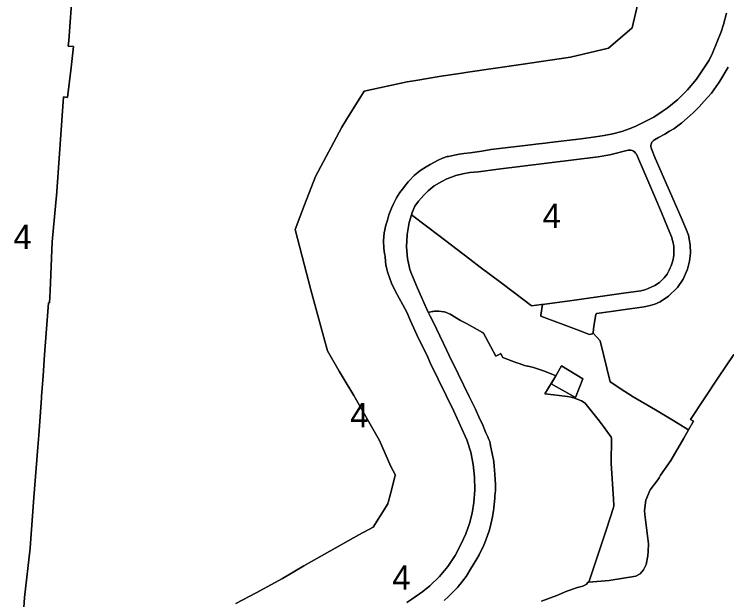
# Model space of a CAD drawing. Extents: x 598968 to 613553, y 4409678 to 4430833.
# Drawn here: x 601272.7 to 601623.1, y 4414130.4 to 4414418.6 of the extents above; entities that cross this region are included whole.
import ezdxf

# ---------------------------------------------------------------- set-up
doc = ezdxf.new("R2010")
doc.units = 0
for name, color, linetype in [('1', 7, 'Continuous'), ('Sòl Rústic Comú', 7, 'Continuous'), ('ZONA 4. CASES UNIFAMILIRAS AÏLLADES EN PARCEL.LES', 7, 'Continuous')]:
    doc.layers.add(name, color=color, linetype=linetype)

msp = doc.modelspace()

# ---------------------------------------------------------------- linework, layer by layer
at = {"layer": '1'}
for points in [[(601301.298, 4414430.8135), (601299.4995, 4414405.7306), (601299.2889, 4414402.9028), (601301.818, 4414402.6437), (601300.6442, 4414392.3584), (601298.958, 4414377.5838), (601296.89, 4414377.9245), (601293.6381, 4414331.4042), (601293.6162, 4414331.165), (601291.3681, 4414306.6243), (601290.2881, 4414282.5045), (601289.9881, 4414276.5945), (601289.5781, 4414276.6145), (601287.5681, 4414250.9247), (601286.8481, 4414240.6598), (601286.1281, 4414230.3949), (601286.0723, 4414229.6282), (601284.7552, 4414211.5161), (601284.3181, 4414205.5051), (601282.4081, 4414180.7053), (601280.4691, 4414156.0453), (601280.4582, 4414155.9054), (601277.7782, 4414131.5456), (601275.9836, 4414104.2898)], [(601381.7065, 4414128.6767), (601391.6574, 4414133.8897), (601404.5462, 4414140.9469), (601415.166, 4414147.1569), (601425.2059, 4414152.807), (601442.1756, 4414162.4271), (601449.1355, 4414166.1871), (601456.3523, 4414177.685), (601456.4433, 4414178.0227), (601456.4854, 4414178.2371), (601457.6811, 4414182.6172), (601460.0848, 4414191.5389), (601460.1326, 4414191.7162), (601457.9353, 4414195.947), (601452.265, 4414208.8867), (601439.6957, 4414231.0065), (601434.5054, 4414239.6885), (601432.5458, 4414242.9663), (601426.8059, 4414253.0162), (601424.9859, 4414259.5461), (601418.5872, 4414282.8915), (601418.5863, 4414282.895), (601410.7762, 4414312.5955), (601415.497, 4414324.8686), (601420.8156, 4414338.6954), (601433.7354, 4414363.0054), (601436.0992, 4414366.8229), (601444.6955, 4414380.7054), (601465.955, 4414385.3255), (601470.1314, 4414386.0296), (601482.6647, 4414388.0957), (601492.8245, 4414389.6058), (601495.7645, 4414390.0158), (601508.1522, 4414391.8435), (601521.8564, 4414393.8693), (601546.2736, 4414397.4963), (601564.9663, 4414401.9773), (601576.573, 4414411.9565), (601579.3492, 4414423.9373)], [(601622.9646, 4414419.1877), (601621.5008, 4414413.6226), (601620.3924, 4414409.9469), (601615.9725, 4414399.427), (601614.4725, 4414396.047), (601608.1609, 4414386.6353), (601603.7928, 4414381.4449), (601598.9521, 4414376.6922), (601593.6825, 4414372.4199), (601591.3335, 4414370.8089), (601587.263, 4414368.0169), (601581.9331, 4414365.2569), (601578.3531, 4414363.5169), (601575.6032, 4414362.3768), (601571.4033, 4414360.8968), (601567.1132, 4414359.7168), (601562.7423, 4414358.8429), (601558.5134, 4414358.2867), (601551.4535, 4414357.2866), (601536.1138, 4414355.4465), (601533.8125, 4414355.1924), (601529.189, 4414354.6231), (601526.7031, 4414354.3256), (601507.0843, 4414351.9562), (601502.6844, 4414351.2462), (601496.9209, 4414350.4625), (601493.8545, 4414350.0461), (601491.4945, 4414349.7161), (601489.1146, 4414349.286), (601486.2581, 4414348.6604), (601485.6147, 4414348.506), (601483.3348, 4414347.736), (601481.1048, 4414346.836), (601477.2849, 4414344.696), (601475.1949, 4414343.4959), (601472.215, 4414341.4659), (601469.425, 4414339.1759), (601466.8551, 4414336.6559), (601466.3951, 4414336.1259), (601464.5651, 4414333.8559), (601464.2054, 4414333.2562), (601462.3451, 4414330.7959), (601460.6852, 4414328.1959), (601459.1708, 4414325.3556), (601458.2326, 4414323.2065), (601456.8652, 4414319.8459), (601456.2608, 4414317.306), (601455.4352, 4414314.766), (601454.6052, 4414311.0164), (601454.2594, 4414307.1917), (601454.4035, 4414303.354), (601454.8236, 4414300.8345), (601455.0354, 4414299.5661), (601455.2454, 4414296.6961), (601455.4554, 4414295.2661), (601455.9054, 4414293.1461), (601456.2954, 4414291.7562), (601457.3554, 4414288.5862), (601458.2554, 4414286.2962), (601460.1153, 4414282.2063), (601463.8453, 4414275.5964), (601465.7652, 4414272.0164), (601467.4852, 4414267.7165), (601470.8952, 4414260.5366), (601474.0051, 4414254.1166), (601475.5351, 4414250.9567), (601477.4626, 4414246.7226), (601488.8561, 4414223.1815), (601495.3236, 4414209.0924), (601497.1498, 4414203.1272), (601498.4008, 4414197.0155), (601499.0652, 4414190.8127), (601499.1371, 4414184.5746), (601498.6158, 4414178.358), (601497.8215, 4414173.0816), (601496.5279, 4414167.9049), (601494.7469, 4414162.8749), (601492.4948, 4414158.0376), (601489.5143, 4414152.2752), (601485.9291, 4414146.8681), (601481.7811, 4414141.8797), (601477.1189, 4414137.3681), (601473.6751, 4414134.4476), (601468.1468, 4414130.6926), (601465.6652, 4414129.0576)], [(601484.1758, 4414130.0728), (601486.3148, 4414132.0478), (601490.6148, 4414136.5278), (601491.1657, 4414137.1617), (601492.6747, 4414138.8978), (601493.1705, 4414139.5816), (601494.8647, 4414141.9178), (601497.0547, 4414145.4578), (601500.2246, 4414150.5678), (601501.2646, 4414152.5278), (601502.3497, 4414154.6626), (601503.2546, 4414156.5178), (601504.5946, 4414159.7878), (601505.5604, 4414162.619), (601506.2706, 4414164.3279), (601506.6956, 4414166.129), (601507.0794, 4414167.7145), (601507.5883, 4414169.8172), (601507.9345, 4414171.2477), (601508.414, 4414174.3133), (601508.5813, 4414175.3833), (601508.5945, 4414175.4677), (601508.9686, 4414180.6387), (601509.0345, 4414181.5376), (601509.3078, 4414184.2659), (601509.2645, 4414187.0076), (601509.1434, 4414189.8545), (601508.855, 4414194.357), (601508.7445, 4414196.0875), (601508.4545, 4414198.4875), (601507.7345, 4414202.3575), (601506.9345, 4414206.2174), (601506.7901, 4414207.3014), (601506.5155, 4414208.36), (601506.1145, 4414209.3774), (601505.5509, 4414210.6098), (601504.6646, 4414212.5473), (601502.7346, 4414217.1473), (601501.7207, 4414219.3501), (601499.4347, 4414224.3171), (601498.1618, 4414226.802), (601497.9747, 4414227.1671), (601496.4322, 4414230.404), (601491.0076, 4414241.6093), (601489.2748, 4414245.0969), (601487.9849, 4414247.5168), (601483.7447, 4414256.6204), (601478.595, 4414267.4766), (601477.252, 4414270.0398), (601476.3951, 4414271.6765), (601476.0951, 4414272.2765), (601471.0322, 4414283.8391), (601468.1157, 4414290.8215), (601467.2302, 4414292.9413), (601466.0927, 4414298.45), (601465.5753, 4414304.0512), (601465.839, 4414310.1533), (601466.8552, 4414316.1761), (601467.9802, 4414319.8611), (601468.3952, 4414320.9961), (601469.7552, 4414324.086), (601471.4752, 4414326.556), (601474.0751, 4414329.636), (601476.2351, 4414331.756), (601479.175, 4414334.1361), (601482.915, 4414336.3561), (601485.4549, 4414337.5661), (601487.6349, 4414338.4461), (601489.8649, 4414339.1961), (601493.2748, 4414340.0762), (601496.7548, 4414340.6462), (601500.9847, 4414341.0662), (601510.6945, 4414342.2763), (601559.8336, 4414348.3868), (601565.6135, 4414349.3668), (601574.5934, 4414351.6969), (601575.2755, 4414351.742), (601575.9551, 4414351.6691), (601576.6121, 4414351.4803), (601577.2267, 4414351.1813), (601577.7808, 4414350.7811), (601578.2577, 4414350.2914), (601578.6433, 4414349.727), (601583.2732, 4414339.1171), (601588.2132, 4414327.5072), (601590.9216, 4414321.0275), (601593.9731, 4414313.7274), (601596.033, 4414308.7975), (601596.2814, 4414307.8177), (601596.623, 4414306.6775), (601596.983, 4414304.4975), (601597.073, 4414303.4075), (601597.073, 4414301.1975), (601596.993, 4414300.1076), (601596.633, 4414297.9276), (601596.073, 4414295.7876), (601595.703, 4414294.7276), (601595.2717, 4414293.7504), (601594.803, 4414292.6776), (601593.6831, 4414290.7376), (601592.3531, 4414288.9376), (601590.0131, 4414286.5376), (601587.7132, 4414285.1576), (601584.4932, 4414283.6076), (601582.8332, 4414282.9575), (601580.8533, 4414282.4575), (601572.2537, 4414281.2743), (601546.9966, 4414277.7523), (601532.498, 4414275.8267), (601532.4941, 4414275.8171), (601531.6541, 4414270.4571), (601531.6341, 4414270.0771), (601549.1338, 4414263.4274), (601555.6137, 4414261.0574), (601556.3237, 4414261.0874), (601556.8637, 4414261.3374), (601557.3037, 4414261.6774), (601557.2937, 4414261.9374), (601557.6437, 4414265.1074), (601558.4914, 4414269.8868), (601558.6436, 4414270.9274), (601558.8936, 4414271.2074), (601559.0636, 4414271.2974), (601559.2436, 4414271.3474), (601582.4542, 4414274.6043), (601585.4232, 4414275.1876), (601587.7032, 4414275.9377), (601590.2918, 4414277.0359), (601594.4626, 4414279.8478), (601598.8209, 4414284.0546), (601601.6619, 4414288.2934), (601603.749, 4414293.1543), (601604.7565, 4414297.0488), (601605.2029, 4414301.0465), (601605.0791, 4414305.0673), (601604.2709, 4414309.8449), (601602.9577, 4414313.2217), (601600.6677, 4414318.6048), (601587.9006, 4414347.7628), (601586.0819, 4414352.3835), (601585.8817, 4414352.9133), (601585.7747, 4414353.4695), (601585.7642, 4414354.0358), (601585.8504, 4414354.5955), (601586.0308, 4414355.1324), (601586.3001, 4414355.6307), (601586.6503, 4414356.0757), (601587.0714, 4414356.4545), (601587.5509, 4414356.756), (601589.5777, 4414357.8808), (601592.6131, 4414359.537), (601594.9849, 4414360.974), (601596.993, 4414362.2071), (601601.0329, 4414365.1471), (601606.5529, 4414370.1071), (601609.4228, 4414373.0471), (601612.0228, 4414375.7571), (601615.5227, 4414379.8071), (601617.8683, 4414383.0965), (601619.7226, 4414385.6971), (601623.7826, 4414392.4771)]]:
    msp.add_lwpolyline(points, dxfattribs=at)
for points in [[(601526.8946, 4414275.2101), (601518.6798, 4414281.4346), (601511.9589, 4414286.5269), (601501.8758, 4414294.1662), (601496.6737, 4414298.1074), (601481.4259, 4414309.6593), (601475.374, 4414314.2368), (601467.9802, 4414319.8611), (601466.8552, 4414316.1761), (601465.839, 4414310.1533), (601465.5753, 4414304.0512), (601466.0927, 4414298.45), (601467.2302, 4414292.9413), (601468.1157, 4414290.8215), (601471.0322, 4414283.8391), (601476.0951, 4414272.2765), (601476.3951, 4414271.6765), (601476.4474, 4414271.7026), (601476.5494, 4414271.7536), (601476.9551, 4414271.9565), (601478.275, 4414272.2965), (601478.7597, 4414272.3474), (601479.3385, 4414272.4082), (601479.895, 4414272.4666), (601481.535, 4414272.4566), (601483.932, 4414272.1816), (601484.1417, 4414272.0716), (601484.1504, 4414272.0697), (601484.7549, 4414271.9166), (601486.3049, 4414271.3866), (601487.0549, 4414271.0566), (601492.1936, 4414267.9489), (601492.4948, 4414267.7667), (601495.1038, 4414266.3189), (601503.0168, 4414261.9276), (601503.5046, 4414261.6569), (601503.507, 4414261.6523), (601507.0746, 4414254.847), (601509.4645, 4414250.287), (601509.5376, 4414250.3227), (601510.1965, 4414250.6446), (601510.782, 4414250.9442), (601512.02, 4414251.5778), (601512.0353, 4414251.543), (601512.876, 4414249.6286), (601515.0696, 4414248.8743), (601515.8544, 4414248.5471), (601519.7572, 4414247.1028), (601520.9343, 4414246.6672), (601523.6243, 4414245.7972), (601525.0274, 4414245.4503), (601525.4368, 4414245.3491), (601528.07, 4414244.6983), (601532.8741, 4414243.0673), (601537.5294, 4414241.2293), (601539.0432, 4414240.6312), (601539.0531, 4414240.6277), (601541.8639, 4414245.5974), (601552.2537, 4414239.1576), (601548.659, 4414230.0451), (601536.794, 4414236.6374), (601539.0217, 4414240.5743), (601533.661, 4414231.7644), (601533.688, 4414231.7157), (601544.8184, 4414230.398), (601546.5277, 4414230.1956), (601547.0578, 4414229.9781), (601547.4338, 4414229.9076), (601551.6137, 4414228.3877), (601552.876, 4414227.5909), (601553.2137, 4414227.3777), (601559.8255, 4414219.0933), (601561.4355, 4414217.076), (601562.4636, 4414215.7879), (601566.1535, 4414210.538), (601566.2124, 4414210.418), (601566.2183, 4414210.406), (601566.4235, 4414209.988), (601566.1435, 4414197.5181), (601567.3057, 4414180.0348), (601567.5235, 4414176.7583), (601567.3747, 4414175.8099), (601563.8744, 4414165.2087), (601555.27, 4414139.1488), (601565.187, 4414139.917), (601565.2122, 4414139.9212), (601578.4166, 4414142.1073), (601580.4315, 4414143.1423), (601582.1464, 4414145.1174), (601583.3864, 4414147.7623), (601584.1814, 4414152.0323), (601584.3443, 4414154.3579), (601584.5964, 4414157.9572), (601582.7064, 4414172.3869), (601582.6464, 4414174.4169), (601583.3064, 4414179.4568), (601585.4663, 4414184.4768), (601589.1752, 4414189.5247), (601589.8686, 4414190.4684), (601590.5462, 4414191.7568), (601595.486, 4414198.8968), (601601.9658, 4414209.9267), (601604.1957, 4414214.1067), (601604.2065, 4414214.1245), (601603.9389, 4414214.2855), (601597.0655, 4414218.4193), (601588.0331, 4414223.8881), (601577.1033, 4414230.3179), (601570.646, 4414234.4823), (601566.4773, 4414237.199), (601565.7545, 4414237.6671), (601560.8336, 4414257.7975), (601557.3037, 4414261.6774), (601556.8637, 4414261.3374), (601556.3237, 4414261.0874), (601555.6137, 4414261.0574), (601549.1338, 4414263.4274), (601531.6341, 4414270.0771), (601531.6541, 4414270.4571), (601532.4941, 4414275.8171), (601532.498, 4414275.8267), (601531.9741, 4414275.7572), (601531.9458, 4414275.7535), (601527.0095, 4414275.123)], [(601539.0217, 4414240.5743), (601536.794, 4414236.6374), (601548.659, 4414230.0451), (601552.2537, 4414239.1576), (601541.8639, 4414245.5974), (601539.0531, 4414240.6277)]]:
    msp.add_lwpolyline(points, close=True, dxfattribs=at)
at = {"layer": 'Sòl Rústic Comú'}
msp.add_lwpolyline([(601626.595, 4414251.1566), (601618.6652, 4414239.4966), (601611.9354, 4414229.3766), (601605.2057, 4414219.2166), (601606.7456, 4414218.2867), (601604.2065, 4414214.1245), (601604.1957, 4414214.1067), (601601.9658, 4414209.9267), (601595.486, 4414198.8968), (601590.5462, 4414191.7568), (601589.8686, 4414190.4684), (601589.1752, 4414189.5247), (601585.4663, 4414184.4768), (601583.3064, 4414179.4568), (601582.6464, 4414174.4169), (601582.7064, 4414172.3869), (601584.5964, 4414157.9572), (601584.3443, 4414154.3579), (601584.1814, 4414152.0323), (601583.3864, 4414147.7623), (601582.1464, 4414145.1174), (601580.4315, 4414143.1423), (601578.4166, 4414142.1073), (601565.2122, 4414139.9212), (601565.187, 4414139.917), (601555.27, 4414139.1488), (601554.9873, 4414139.1268), (601554.0074, 4414137.9568), (601552.3274, 4414137.2068), (601549.6904, 4414136.4823), (601544.3776, 4414134.5967), (601539.4378, 4414132.5966), (601531.9781, 4414129.7365)], dxfattribs=at)
at = {"layer": 'ZONA 4. CASES UNIFAMILIRAS AÏLLADES EN PARCEL.LES'}
for points in [[(601275.9836, 4414104.2898), (601277.7782, 4414131.5456), (601280.4582, 4414155.9054), (601280.4691, 4414156.0453), (601282.4081, 4414180.7053), (601284.3181, 4414205.5051), (601284.7552, 4414211.5161), (601286.0723, 4414229.6282), (601286.1281, 4414230.3949), (601286.8481, 4414240.6598), (601287.5681, 4414250.9247), (601289.5781, 4414276.6145), (601289.9881, 4414276.5945), (601290.2881, 4414282.5045), (601291.3681, 4414306.6243), (601293.6162, 4414331.165), (601293.6381, 4414331.4042), (601296.89, 4414377.9245), (601298.958, 4414377.5838), (601300.6442, 4414392.3584), (601301.818, 4414402.6437), (601299.2889, 4414402.9028), (601299.4995, 4414405.7306), (601301.298, 4414430.8135)], [(601579.3492, 4414423.9373), (601576.573, 4414411.9565), (601564.9663, 4414401.9773), (601546.2736, 4414397.4963), (601521.8564, 4414393.8693), (601508.1522, 4414391.8435), (601495.7645, 4414390.0158), (601492.8245, 4414389.6058), (601482.6647, 4414388.0957), (601470.1314, 4414386.0296), (601465.955, 4414385.3255), (601444.6955, 4414380.7054), (601436.0992, 4414366.8229), (601433.7354, 4414363.0054), (601420.8156, 4414338.6954), (601415.497, 4414324.8686), (601410.7762, 4414312.5955), (601418.5863, 4414282.895), (601418.5872, 4414282.8915), (601424.9859, 4414259.5461), (601426.8059, 4414253.0162), (601432.5458, 4414242.9663), (601434.5054, 4414239.6885), (601439.6957, 4414231.0065), (601452.265, 4414208.8867), (601457.9353, 4414195.947), (601460.1326, 4414191.7162), (601460.0848, 4414191.5389), (601457.6811, 4414182.6172), (601456.4854, 4414178.2371), (601456.4433, 4414178.0227), (601456.3523, 4414177.685), (601449.1355, 4414166.1871), (601442.1756, 4414162.4271), (601425.2059, 4414152.807), (601415.166, 4414147.1569), (601404.5462, 4414140.9469), (601391.6574, 4414133.8897), (601381.7065, 4414128.6767)], [(601465.6652, 4414129.0576), (601468.1468, 4414130.6926), (601473.6751, 4414134.4476), (601477.1189, 4414137.3681), (601481.7811, 4414141.8797), (601485.9291, 4414146.8681), (601489.5143, 4414152.2752), (601492.4948, 4414158.0376), (601494.7469, 4414162.8749), (601496.5279, 4414167.9049), (601497.8215, 4414173.0816), (601498.6158, 4414178.358), (601499.1371, 4414184.5746), (601499.0652, 4414190.8127), (601498.4008, 4414197.0155), (601497.1498, 4414203.1272), (601495.3236, 4414209.0924), (601488.8561, 4414223.1815), (601477.4626, 4414246.7226), (601475.5351, 4414250.9567), (601474.0051, 4414254.1166), (601470.8952, 4414260.5366), (601467.4852, 4414267.7165), (601465.7652, 4414272.0164), (601463.8453, 4414275.5964), (601460.1153, 4414282.2063), (601458.2554, 4414286.2962), (601457.3554, 4414288.5862), (601456.2954, 4414291.7562), (601455.9054, 4414293.1461), (601455.4554, 4414295.2661), (601455.2454, 4414296.6961), (601455.0354, 4414299.5661), (601454.8236, 4414300.8345), (601454.4035, 4414303.354), (601454.2594, 4414307.1917), (601454.6052, 4414311.0164), (601455.4352, 4414314.766), (601456.2608, 4414317.306), (601456.8652, 4414319.8459), (601458.2326, 4414323.2065), (601459.1708, 4414325.3556), (601460.6852, 4414328.1959), (601462.3451, 4414330.7959), (601464.2054, 4414333.2562), (601464.5651, 4414333.8559), (601466.3951, 4414336.1259), (601466.8551, 4414336.6559), (601469.425, 4414339.1759), (601472.215, 4414341.4659), (601475.1949, 4414343.4959), (601477.2849, 4414344.696), (601481.1048, 4414346.836), (601483.3348, 4414347.736), (601485.6147, 4414348.506), (601486.2581, 4414348.6604), (601489.1146, 4414349.286), (601491.4945, 4414349.7161), (601493.8545, 4414350.0461), (601496.9209, 4414350.4625), (601502.6844, 4414351.2462), (601507.0843, 4414351.9562), (601526.7031, 4414354.3256), (601529.189, 4414354.6231), (601533.8125, 4414355.1924), (601536.1138, 4414355.4465), (601551.4535, 4414357.2866), (601558.5134, 4414358.2867), (601562.7423, 4414358.8429), (601567.1132, 4414359.7168), (601571.4033, 4414360.8968), (601575.6032, 4414362.3768), (601578.3531, 4414363.5169), (601581.9331, 4414365.2569), (601587.263, 4414368.0169), (601591.3335, 4414370.8089), (601593.6825, 4414372.4199), (601598.9521, 4414376.6922), (601603.7928, 4414381.4449), (601608.1609, 4414386.6353), (601614.4725, 4414396.047), (601615.9725, 4414399.427), (601620.3924, 4414409.9469), (601621.5008, 4414413.6226), (601622.9646, 4414419.1877)], [(601623.7826, 4414392.4771), (601619.7226, 4414385.6971), (601617.8683, 4414383.0965), (601615.5227, 4414379.8071), (601612.0228, 4414375.7571), (601609.4228, 4414373.0471), (601606.5529, 4414370.1071), (601601.0329, 4414365.1471), (601596.993, 4414362.2071), (601594.9849, 4414360.974), (601592.6131, 4414359.537), (601589.5777, 4414357.8808), (601587.5509, 4414356.756), (601587.0714, 4414356.4545), (601586.6503, 4414356.0757), (601586.3001, 4414355.6307), (601586.0308, 4414355.1324), (601585.8504, 4414354.5955), (601585.7642, 4414354.0358), (601585.7747, 4414353.4695), (601585.8817, 4414352.9133), (601586.0819, 4414352.3835), (601587.9006, 4414347.7628), (601600.6677, 4414318.6048), (601602.9577, 4414313.2217), (601604.2709, 4414309.8449), (601605.0791, 4414305.0673), (601605.2029, 4414301.0465), (601604.7565, 4414297.0488), (601603.749, 4414293.1543), (601601.6619, 4414288.2934), (601598.8209, 4414284.0546), (601594.4626, 4414279.8478), (601590.2918, 4414277.0359), (601587.7032, 4414275.9377), (601585.4232, 4414275.1876), (601582.4542, 4414274.6043), (601559.2436, 4414271.3474), (601559.0636, 4414271.2974), (601558.8936, 4414271.2074), (601558.6436, 4414270.9274), (601558.4914, 4414269.8868), (601557.6437, 4414265.1074), (601557.2937, 4414261.9374), (601557.3037, 4414261.6774), (601560.8336, 4414257.7975), (601565.7545, 4414237.6671), (601566.4773, 4414237.199), (601570.646, 4414234.4823), (601577.1033, 4414230.3179), (601588.0331, 4414223.8881), (601597.0655, 4414218.4193), (601603.9389, 4414214.2855), (601604.2065, 4414214.1245), (601606.7456, 4414218.2867), (601605.2057, 4414219.2166), (601611.9354, 4414229.3766), (601618.6652, 4414239.4966), (601626.595, 4414251.1566)], [(601531.9781, 4414129.7365), (601539.4378, 4414132.5966), (601544.3776, 4414134.5967), (601549.6904, 4414136.4823), (601552.3274, 4414137.2068), (601554.0074, 4414137.9568), (601554.9873, 4414139.1268), (601555.27, 4414139.1488), (601563.8744, 4414165.2087), (601567.3747, 4414175.8099), (601567.5235, 4414176.7583), (601567.3057, 4414180.0348), (601566.1435, 4414197.5181), (601566.4235, 4414209.988), (601566.2183, 4414210.406), (601566.2124, 4414210.418), (601566.1535, 4414210.538), (601562.4636, 4414215.7879), (601561.4355, 4414217.076), (601559.8255, 4414219.0933), (601553.2137, 4414227.3777), (601552.876, 4414227.5909), (601551.6137, 4414228.3877), (601547.4338, 4414229.9076), (601547.0578, 4414229.9781), (601546.5277, 4414230.1956), (601544.8184, 4414230.398), (601533.688, 4414231.7157), (601533.661, 4414231.7644), (601539.0217, 4414240.5743), (601539.0531, 4414240.6277), (601539.0432, 4414240.6312), (601537.5294, 4414241.2293), (601532.8741, 4414243.0673), (601528.07, 4414244.6983), (601525.4368, 4414245.3491), (601525.0274, 4414245.4503), (601523.6243, 4414245.7972), (601520.9343, 4414246.6672), (601519.7572, 4414247.1028), (601515.8544, 4414248.5471), (601515.0696, 4414248.8743), (601512.876, 4414249.6286), (601512.0353, 4414251.543), (601512.02, 4414251.5778), (601510.782, 4414250.9442), (601510.1965, 4414250.6446), (601509.5376, 4414250.3227), (601509.4645, 4414250.287), (601507.0746, 4414254.847), (601503.507, 4414261.6523), (601503.5046, 4414261.6569), (601503.0168, 4414261.9276), (601495.1038, 4414266.3189), (601492.4948, 4414267.7667), (601492.1936, 4414267.9489), (601487.0549, 4414271.0566), (601486.3049, 4414271.3866), (601484.7549, 4414271.9166), (601484.1504, 4414272.0697), (601484.1417, 4414272.0716), (601483.932, 4414272.1816), (601481.535, 4414272.4566), (601479.895, 4414272.4666), (601479.3385, 4414272.4082), (601478.7597, 4414272.3474), (601478.275, 4414272.2965), (601476.9551, 4414271.9565), (601476.5494, 4414271.7536), (601476.4474, 4414271.7026), (601476.3951, 4414271.6765), (601477.252, 4414270.0398), (601478.595, 4414267.4766), (601483.7447, 4414256.6204), (601487.9849, 4414247.5168), (601489.2748, 4414245.0969), (601491.0076, 4414241.6093), (601496.4322, 4414230.404), (601497.9747, 4414227.1671), (601498.1618, 4414226.802), (601499.4347, 4414224.3171), (601501.7207, 4414219.3501), (601502.7346, 4414217.1473), (601504.6646, 4414212.5473), (601505.5509, 4414210.6098), (601506.1145, 4414209.3774), (601506.5155, 4414208.36), (601506.7901, 4414207.3014), (601506.9345, 4414206.2174), (601507.7345, 4414202.3575), (601508.4545, 4414198.4875), (601508.7445, 4414196.0875), (601508.855, 4414194.357), (601509.1434, 4414189.8545), (601509.2645, 4414187.0076), (601509.3078, 4414184.2659), (601509.0345, 4414181.5376), (601508.9686, 4414180.6387), (601508.5945, 4414175.4677), (601508.5813, 4414175.3833), (601508.414, 4414174.3133), (601507.9345, 4414171.2477), (601507.5883, 4414169.8172), (601507.0794, 4414167.7145), (601506.6956, 4414166.129), (601506.2706, 4414164.3279), (601505.5604, 4414162.619), (601504.5946, 4414159.7878), (601503.2546, 4414156.5178), (601502.3497, 4414154.6626), (601501.2646, 4414152.5278), (601500.2246, 4414150.5678), (601497.0547, 4414145.4578), (601494.8647, 4414141.9178), (601493.1705, 4414139.5816), (601492.6747, 4414138.8978), (601491.1657, 4414137.1617), (601490.6148, 4414136.5278), (601486.3148, 4414132.0478), (601484.1758, 4414130.0728)]]:
    msp.add_lwpolyline(points, dxfattribs=at)
msp.add_lwpolyline([(601532.498, 4414275.8267), (601546.9966, 4414277.7523), (601572.2537, 4414281.2743), (601580.8533, 4414282.4575), (601582.8332, 4414282.9575), (601584.4932, 4414283.6076), (601587.7132, 4414285.1576), (601590.0131, 4414286.5376), (601592.3531, 4414288.9376), (601593.6831, 4414290.7376), (601594.803, 4414292.6776), (601595.2717, 4414293.7504), (601595.703, 4414294.7276), (601596.073, 4414295.7876), (601596.633, 4414297.9276), (601596.993, 4414300.1076), (601597.073, 4414301.1975), (601597.073, 4414303.4075), (601596.983, 4414304.4975), (601596.623, 4414306.6775), (601596.2814, 4414307.8177), (601596.033, 4414308.7975), (601593.9731, 4414313.7274), (601590.9216, 4414321.0275), (601588.2132, 4414327.5072), (601583.2732, 4414339.1171), (601578.6433, 4414349.727), (601578.2577, 4414350.2914), (601577.7808, 4414350.7811), (601577.2267, 4414351.1813), (601576.6121, 4414351.4803), (601575.9551, 4414351.6691), (601575.2755, 4414351.742), (601574.5934, 4414351.6969), (601565.6135, 4414349.3668), (601559.8336, 4414348.3868), (601510.6945, 4414342.2763), (601500.9847, 4414341.0662), (601496.7548, 4414340.6462), (601493.2748, 4414340.0762), (601489.8649, 4414339.1961), (601487.6349, 4414338.4461), (601485.4549, 4414337.5661), (601482.915, 4414336.3561), (601479.175, 4414334.1361), (601476.2351, 4414331.756), (601474.0751, 4414329.636), (601471.4752, 4414326.556), (601469.7552, 4414324.086), (601468.3952, 4414320.9961), (601467.9802, 4414319.8611), (601475.374, 4414314.2368), (601481.4259, 4414309.6593), (601496.6737, 4414298.1074), (601501.8758, 4414294.1662), (601511.9589, 4414286.5269), (601518.6798, 4414281.4346), (601526.8946, 4414275.2101), (601527.0095, 4414275.123), (601531.9458, 4414275.7535), (601531.9741, 4414275.7572)], close=True, dxfattribs=at)

# ---------------------------------------------------------------- texts
for p in [(601532.5266, 4414313.4325), (601272.3287, 4414303.114), (601437.8967, 4414215.2779), (601458.6118, 4414135.3954)]:
    msp.add_text('4', height=12, dxfattribs=at).set_placement(p)

doc.saveas('drawing.dxf')
